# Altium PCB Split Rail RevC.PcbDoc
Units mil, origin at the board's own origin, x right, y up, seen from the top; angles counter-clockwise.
Board outline 1500 x 1405 mil, 2 copper layers (Top Layer, Bottom Layer); 41 components, 22 nets, 98 pads, 37 vias.
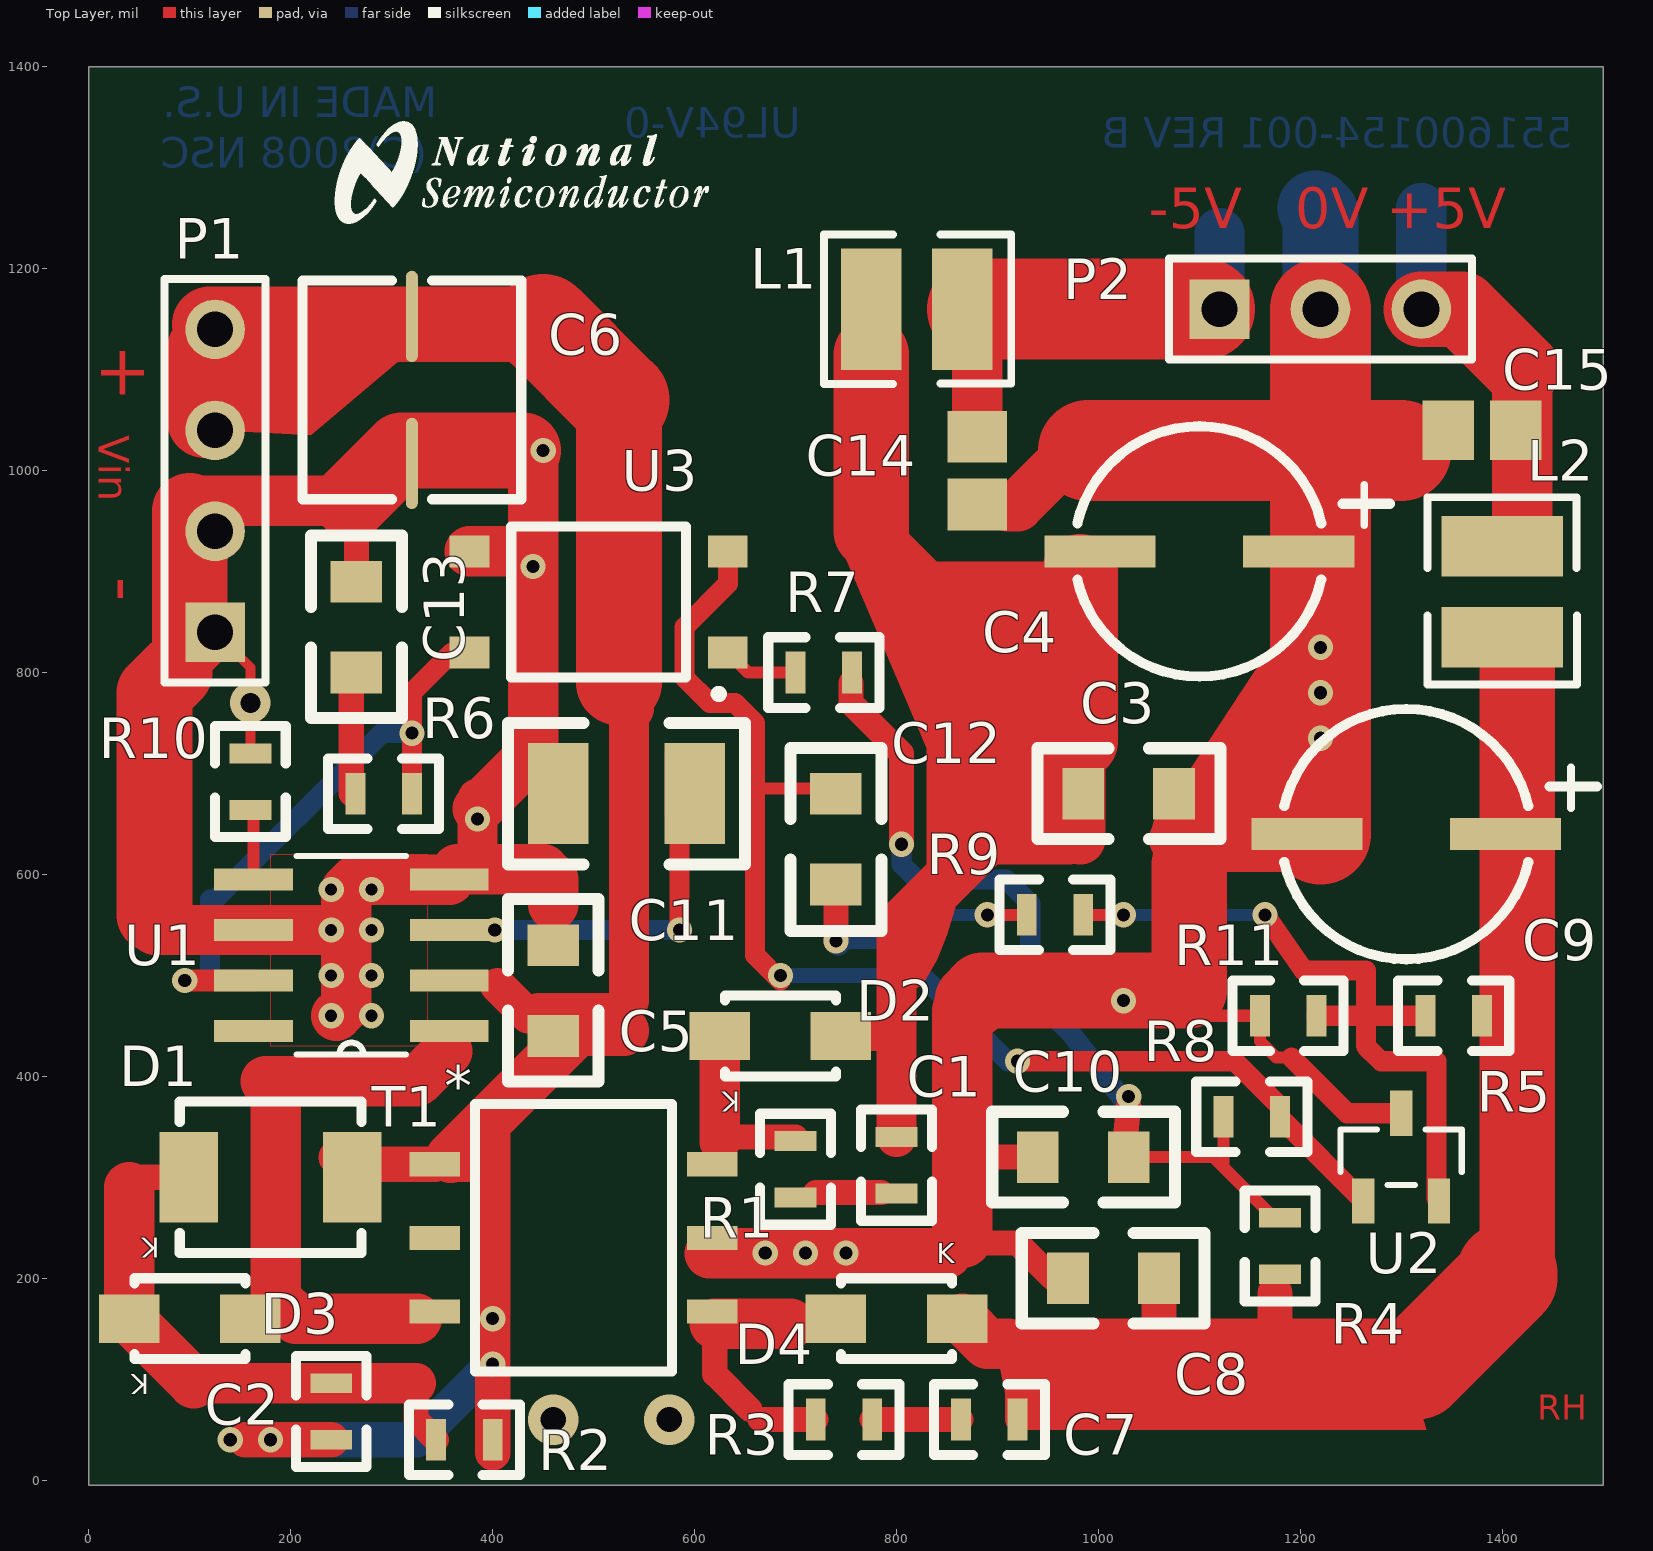
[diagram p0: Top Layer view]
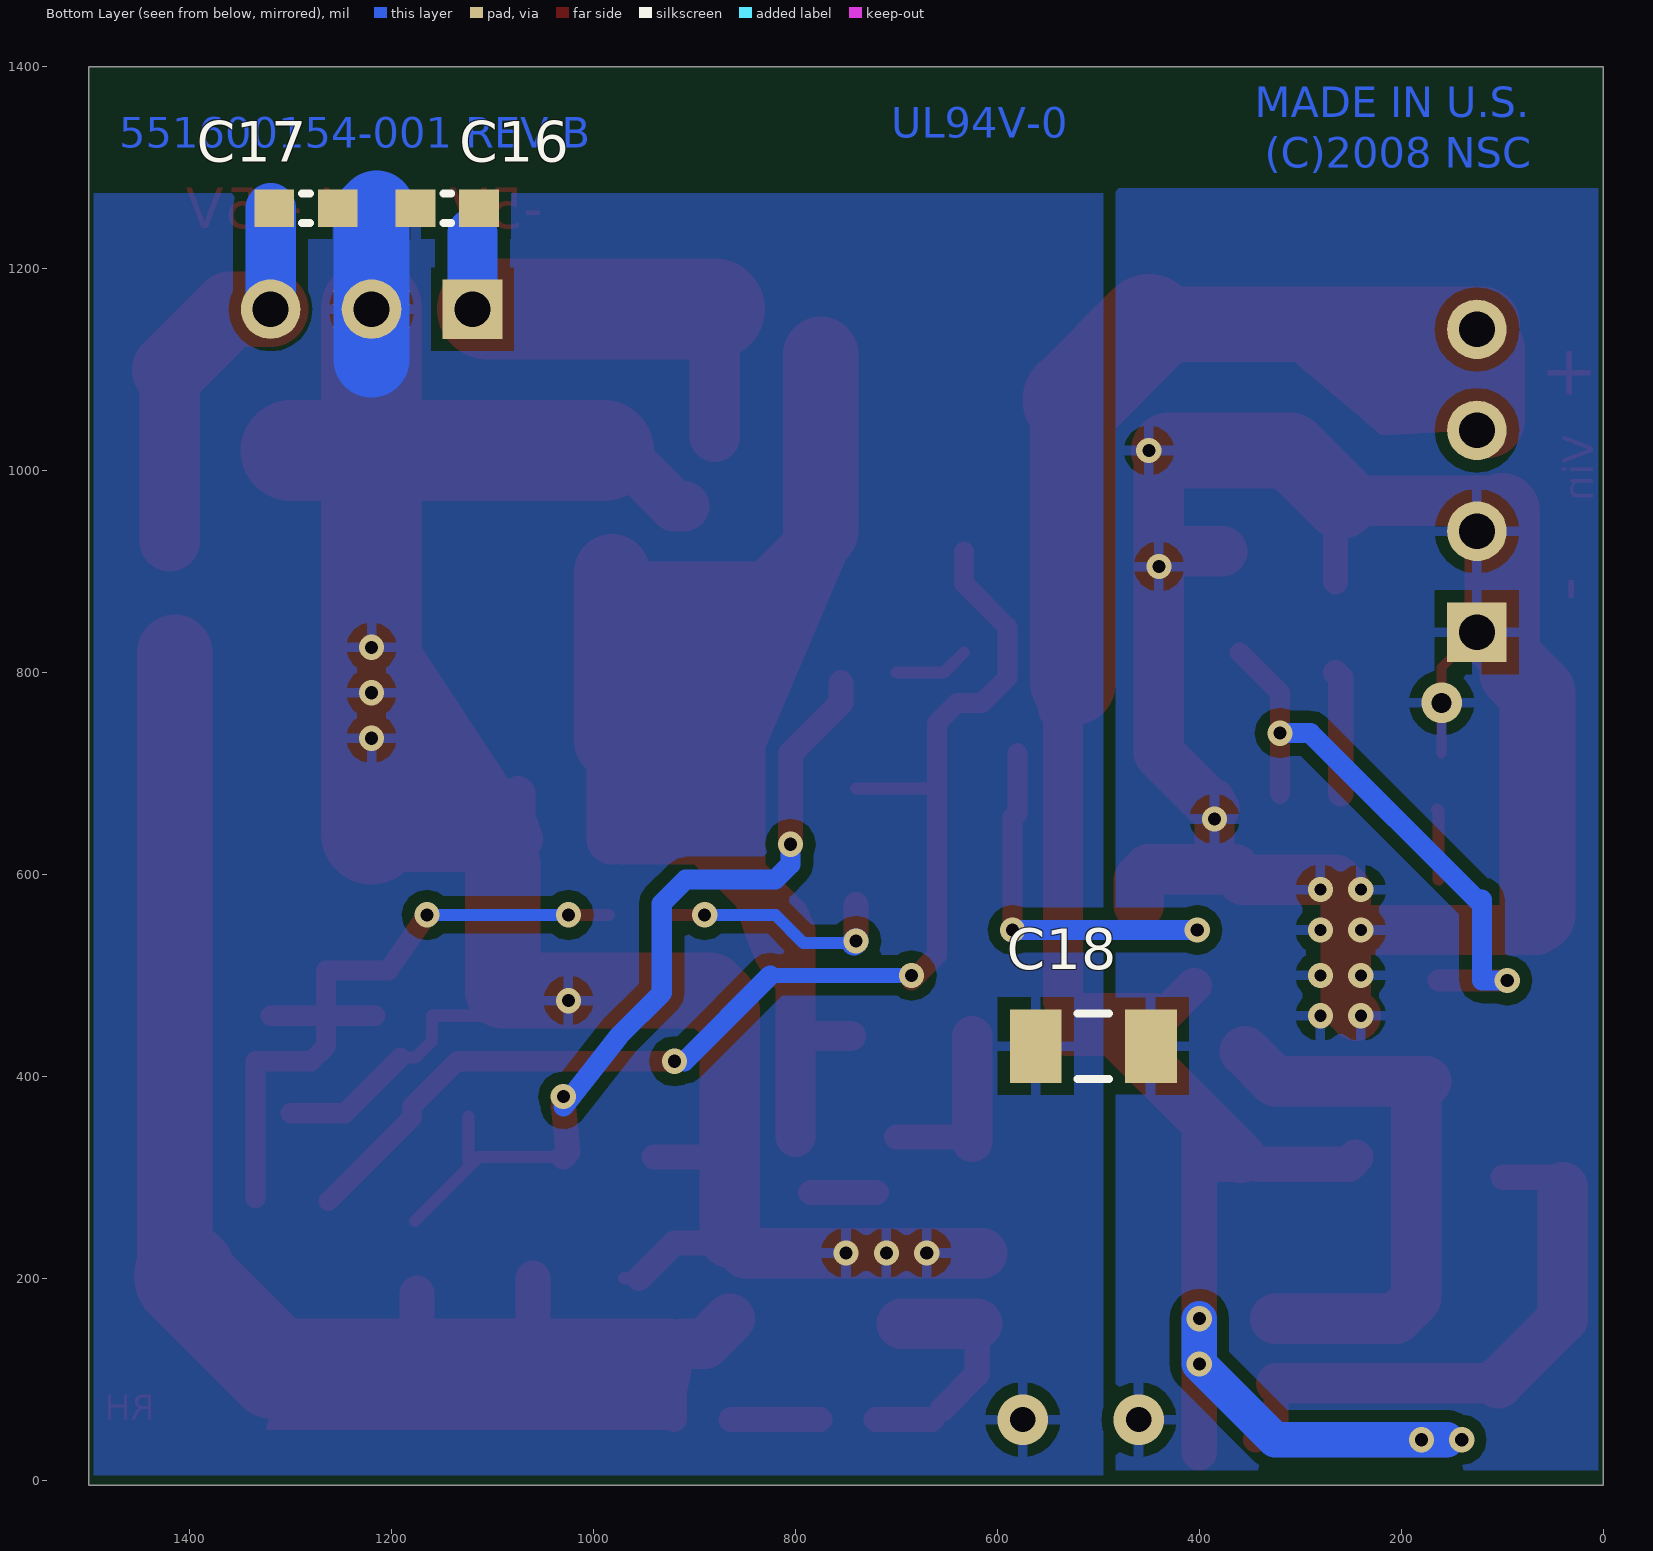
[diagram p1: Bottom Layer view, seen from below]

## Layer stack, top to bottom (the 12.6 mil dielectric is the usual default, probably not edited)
Top Layer: signal copper 1.4
Dielectric: core 12.6, FR-4, Dk 4.8
Bottom Layer: signal copper 1.4

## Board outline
0,-5 0,1400 1500,1400 1500,-5

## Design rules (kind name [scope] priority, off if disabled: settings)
Clearance "DC Power <25W" [All] p1: gap=12
Clearance [All] p2: gap=5
ComponentClearance [All] p1: gap=10 collisioncheckmode=0 verticalgap=10
PolygonConnect [All] p1: connectstyle=Relief reliefconductorwidth=10 reliefentries=4 polygonreliefangle="90 Angle"
RoutingVias [All] p1: holewidth=13 width=25 viastyle="Through Hole" minholewidth=12 minwidth=25 maxholewidth=28 maxwidth=50
SMDNeckDown [All] p1: percent=750.000
SolderMaskExpansion [All] p1: expansion=4
TestPointUsage [All] p1: valid=0 allowmultiple=FALSE
Testpoint [All] p1: side=15 testpointundercomponent=TRUE minsize=10 maxsize=100 preferedsize=60 minholesize=0 maxholesize=40 preferedholesize=32 testpointgrid=1 style=1023 order=0-112345678
Width "Schematic Width Constraint" [InNet('NetC2_1')] p1: maxlimit=100 minlimit=10 preferedwidth=40
Width Ground_Out [InNet('NetC3_2')] p2: maxlimit=100 minlimit=10 preferedwidth=50
Width Ground_In [InNet('GND')] p3: maxlimit=100 minlimit=10 preferedwidth=35
Width [All] p4: maxlimit=200 minlimit=10 preferedwidth=20
18 further rules are at their usual default settings.

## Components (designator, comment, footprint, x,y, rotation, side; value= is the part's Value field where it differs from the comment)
C1 "WB_CAPACITOR" 0603#1 800,340 r270 top
C2 "WB_CAPACITOR" 0603#1 240,40 r90 top
C3 "WB_CAPACITOR" 0805#1 985,680 r0 top
C4 "WB_CAP_POLARIZED" SM_RADIAL_D 1100,920 r90 top
C5 "WB_CAPACITOR" 0805#1 460,440 r90 top
C6 "WB_CAP_POLARIZED" MZA 320,1080 r180 top
C7 "WB_CAPACITOR" 0603#1 920,60 r180 top
C8 "WB_CAPACITOR" 0805#1 1060,200 r180 top
C9 "WB_CAP_POLARIZED" SM_RADIAL_D 1305,640 r90 top
C10 "WB_CAPACITOR" 0805#1 940,320 r0 top
C11 "WB_CAPACITOR" 1210 600,680 r180 top
C12 "WB_CAPACITOR" 0805#1 740,680 r270 top
C13 "WB_CAPACITOR" 0805#1 265,800 r90 top
C14 "WB_CAPACITOR" 0805#2 880,1000 r270 top
C15 "WB_CAPACITOR" 0805#2 1380,1040 r0 top
C16 "WB_CAPACITOR" 0603#2 1145,1260 r0 bottom
C17 "WB_CAPACITOR" 0603#2 1285,1260 r0 bottom
C18 "WB_CAPACITOR" 1206 505,430 r180 bottom
D1 "33V Zener, SMB, 1Wmin" SMB 180,300 r180 top
D2 "WB_DIODE_SCHOTTKY" SOD-123 685,440 r180 top
D3 "BAT41ZFILM" SOD-123 100,160 r180 top
D4 "WB_DIODE_SCHOTTKY" SOD-123 800,160 r0 top
L1 "WB_INDUCTOR" ME3220 820,1160 r180 top
L2 "WB_INDUCTOR" ME3220 1400,880 r270 top
P1 "Header 4" HDR1X4 125,840 r90 top
P2 "Header 3" HDR1X3 1120,1160 r0 top
R1 "WB_Resistor" 0603#1 700,280 r90 top
R2 "WB_Resistor" 0603#1 400,40 r180 top
R3 "WB_Resistor" 0603#1 775.98,60 r180 top
R4 "WB_Resistor" 0603#1 1180,260 r270 top
R5 "WB_Resistor" 0603#1 1380,460 r180 top
R6 "WB_Resistor" 0603#1 320,680 r180 top
R7 "WB_Resistor" 0603#1 700,800 r0 top
R8 "WB_Resistor" 0603#1 1180,360 r180 top
R9 "WB_Resistor" 0603#1 985,560 r180 top
R10 "WB_Resistor" 0603#1 160,720 r270 top
R11 "WB_Resistor" 0603#1 1160,460 r0 top
T1 "RENCO_EP5" S32890 480,240 r0 top
U1 "LM5001MA" M08A 260,520 r180 top
U2 "LM431Z" MF03A 1300,320 r0 top
U3 "FODM121" FOD121 505,870 r180 top

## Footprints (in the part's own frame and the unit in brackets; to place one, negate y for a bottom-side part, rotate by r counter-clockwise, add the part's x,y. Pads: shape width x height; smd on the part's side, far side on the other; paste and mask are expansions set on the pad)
0603#1 [mm]
  rect 0.5x1.05 smd: 1(0,0) 2(1.422,0)
  silkscreen extent -0.69,-0.89 2.11,0.89
0603#2 [mm] "0603 from SM-752 data"
  rect 1x0.95 smd: 1(-0.8,0) 2(0.8,0)
  silkscreen extent -0.1,-0.38 0.1,0.38, body extent -0.88,-0.48 0.87,0.48, height 0.85
0805#1 [mm]
  rect 1.05x1.3 smd: 1(0,0) 2(2.286,0)
  silkscreen extent -1.15,-1.14 3.45,1.14
0805#2 [mm] "0805 from SM-752 data"
  rect 1.3x1.5 smd: 1(-0.85,0) 2(0.85,0)
  body extent -1.1,-0.72 1.1,0.72, height 1.1
1206 [mm] "1206 from SM-752 data"
  rect 1.3x1.85 smd: 1(-1.45,0) 2(1.45,0)
  silkscreen extent -0.4,-0.82 0.4,0.82, body extent -1.7,-0.9 1.7,0.9, height 1.35
1210 [mil]
  rect 60x100 smd: 1(0,0) 2(135,0)
  silkscreen extent -50,-70 185,70
FOD121 [mm] "Fairchild OptoCoupler"
  rect 1x0.8 smd: 1(-3.25,1.27) 2(-3.25,-1.27) 3(3.25,-1.27) 4(3.25,1.27)
  silkscreen extent -3.1,-1.9 2.2,2.39, body extent -3.85,-2.03 3.85,2.03, height 2.3
HDR1X3 [mm] "Connector; Header; 3 Position"
  rect 1.5x1.5 hole 0.9: 1(0,0)
  round 1.5 hole 0.9: 2(2.54,0) 3(5.08,0)
  silkscreen extent -1.27,-1.27 6.35,1.27
HDR1X4 [mm] "Connector; Header; 4 Position"
  rect 1.5x1.5 hole 0.9: 1(0,0)
  round 1.5 hole 0.9: 2(2.54,0) 3(5.08,0) 4(7.62,0)
  silkscreen extent -1.27,-1.27 8.89,1.27
M08A [mil]
  rect 78x22 smd: 1(-97,75) 2(-97,25) 3(-97,-25) 4(-97,-75) 5(97,-75) 6(97,-25) 7(97,25) 8(97,75)
  silkscreen extent -54,-98 54,98
ME3220 [mm] "Coilcraft SMT Power Inductor ME3220 inductors"
  rect 1.52x3.05 smd: 1(-1.145,0) 2(1.145,0)
  silkscreen extent -2.38,-1.88 2.34,1.88, body extent -1.75,-1.41 1.75,1.4
MF03A [mil]
  rect 22x45 smd: 1(-37.5,-43.5) 2(37.5,-43.5) 3(0,43.5)
  silkscreen extent -60,-28 60,28
MZA [mm]
  oval 0.3x2.3 smd: 1(0,-1.85) 2(0,1.85)
  silkscreen extent -2.75,-2.75 2.75,2.75
S32890 [mm]
  rect 1.27x0.61 smd: 1(-3.493,1.854) 2(-3.493,0) 3(-3.493,-1.854) 4(3.493,-1.854) 5(3.493,0) 6(3.493,1.854)
  silkscreen extent -2.47,-3.36 2.47,3.36
SM_RADIAL_D [mm] "SM_RADIAL_D"
  rect 0.8x2.8 smd: 1(0,-2.5) 2(0,2.5)
  silkscreen extent -3.15,-4.8 3.15,3.07
SMB [mil]
  rect 58x90 smd: 1(-81,0) 2(81,0)
  silkscreen extent -90,-75 90,75
SOD-123 [mil]
  rect 60x48 smd: 1(-60,0) 2(60,0)
  silkscreen extent -55,-40 55,40

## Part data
C1 C7: library part 06035A221JAT2A, "Capacitor"
C2: library part GRM188R71H103KA01D, "Capacitor"
C3 C5 C8 C12 C13: library part C0805C104J5RACTU, "Capacitor"
C4 C9: library part EEV-FK1C470P, "Polarized Capacitor"
C6: library part EMZA500ADA100ME61G, "Polarized Capacitor"
C10: library part TMK212BJ105KG-T, "Capacitor"
C11: library part GRM32RR71H105K, "Capacitor"
C14 C15: library part EMK212BJ106KG-T, "Capacitor"
C16 C17: library part C1608X7R1H103K, "Capacitor"
C18: library part C3216C0G2J332J, "Capacitor"
D1: library part 10BQ100TRPBF, "Schottky Diode"
D2 D3 D4: library part 1N5819HW-7, "Schottky Diode"
L1 L2: library part ME3220-102MLB, "Inductor"
P1: "Header, 4-Pin"
P2: "Header, 3-Pin"
R1 R3: library part CRCW0603120RJNEA, "Resistor"
R2 R8: library part CRCW060310k0JNEA, "Resistor"
R4: library part CRCW060347R0JNEA, "Resistor"
R5 R11: library part CRCW06032k20JNEA, "Resistor"
R6: library part CRCW0603249RFKEA, "Resistor"
R7: library part CRCW0603560RJNEA, "Resistor"
R9: library part CRCW06034k99FKEA, "Resistor"
R10: library part CRCW060320k5FKEA, "Resistor"
T1: "Transformer"
U1: "High Voltage Switch Mode Regulator"
U2: library part LM431CCM3, "Adjustable Precision Zener Shunt Regulator"
U3: "Full Pitch Mini-Flat Package Transistor Output  Optocoupler"

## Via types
v1: diameter 25, hole 13, Top Layer to Bottom Layer, 26 vias
v2: diameter 25, hole 12, Top Layer to Bottom Layer, 8 vias
v3: diameter 50, hole 25, Top Layer to Bottom Layer, 2 vias
v4: diameter 40, hole 20, Top Layer to Bottom Layer, 1 vias

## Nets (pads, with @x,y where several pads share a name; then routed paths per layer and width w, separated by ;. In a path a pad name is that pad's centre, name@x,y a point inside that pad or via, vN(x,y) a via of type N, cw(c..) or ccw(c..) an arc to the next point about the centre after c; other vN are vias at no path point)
GND: C5.2 C6.2 C11.2 C13.2 C18.2 P1.1 P1.2 R10.1 U1.4 U1.6 U3.3 | length 2006.5
  Top Layer w10: P1.1 160,805 R10.1
  Top Layer w25: C13.2 265,975
  Top Layer w40: 385,615 385,675
  Top Layer w50: 65,545 v2(240,545) ; 85,800 P1.1 ; 105,970 260,970 ; v2@245,460 255,470 255,585 265,595 U1.4 ; U1.4@365,605 450,605 460,595 460,570 ; U3.3 425,920 ; v1@385,665 440,720 440,1010
  Top Layer w75: 65,560 65,780 85,800 ; P1.1@100,833.75 100,960 ; 260,970 310,1020 430,1020
  other v1: 385,655 440,905 450,1020
  other v2: 240,460 280,460 240,500 280,500 280,545 240,585 280,585
  other v3: 460,60
  other v4: 160,770
NetC1_1: C1.1 C3.1 C4.2 D2.1 L1.2 | length 1083
  Top Layer w30: D2.1 790,440
  Top Layer w40: C1.1 800,545
  Top Layer w50: 775,940 830,885 950,885 ; 810,555 895,640 ; 981.85,635 981.85,731.85
  Top Layer w60: 895,640 970,640
  Top Layer w75: 775,940 L1.2@775,1115 ; 981.85,731.85 981.85,900
NetC1_2: C1.2 R1.1 | length 65
  Top Layer w25: R1.1@720,285 C1.2@785,285
NetC2_1: C2.1 C5.1 C6.1 D1.1 P1.3 P1.4 R2.1 T1.1 U1.2 | length 2315.7
  Top Layer w35: P1.3@115,1050 P1.3 ; 155,40 C2.1 ; D1.1@245,320 252,313 T1.1 ; T1.1@358.44,319.61 361.18,313 400,313 ; R2.1@400,27 400,340 ; 405,490 C5.1@435,460 ; 445,465 525,465
  Top Layer w40: 535,475 535,765
  Top Layer w50: T1.1@358.44,319.61 483.83,445 530,445 ; 525,775 535,765
  Top Layer w75: P1.3@115,1050 P1.4@115,1120 ; P1.4@120,1145 450,1145
  Top Layer w85: 525,790 525,1070
  Top Layer w100: 450,1145 525,1070
  Bottom Layer w35: 155,40 325,40 v1(400,115) v1(400,160)
  other v1: 140,40 180,40
NetC2_2: C2.2 D1.2 D3.2 R2.2 | length 567.9
  Top Layer w25: 40,290 50,300 D1.2 ; 324.02,95.98 324.02,60 R2.2
  Top Layer w40: 104.02,95.98 324.02,95.98
  Top Layer w50: 40,290 D3.2 104.02,95.98
NetC3_2: C3.2 C4.1 C8.2 C9.2 C10.1 C14.2 C15.1 C16.2 C17.1 C18.1 P2.2 R11.1 T1.5 U2.3 | length 2650.5
  Top Layer w12: C8.2@955,200 C8.2 ; 1067.5,490 1097.5,460 ; 1090,485 1100,500 ; 1092.5,460 R11.1 1160,435 1176.25,418.75 1191.25,418.75
  Top Layer w20: 1191.25,418.75 1246.5,363.5 U2.3
  Top Layer w25: 830,235 920,235 C8.2@955,200 ; 865,320 C10.1
  Top Layer w35: 1075,635 C3.2
  Top Layer w50: 615,225 850,225 ; 865,465 875,475 ; 910,965 920,965 995,1040 ; 1075,635 1080,640
  Top Layer w60: 865,240 865,465
  Top Layer w75: 875,475 885,485 1090,485 1090,610 ; 1090,640 C9.2@1220,640
  Top Layer w100: 990,1020 1300,1020 ; C9.2@1220,640 P2.2
  Bottom Layer w75: 1215,1260 1220,1255 1220,1110.07
  other v1: 670,225 710,225 750,225 1025,475 1220,735 1220,780 1220,825
  other v3: 575,60
NetC7_1: C7.1 C8.1 C9.1 D4.2 L2.2 R4.2 R5.1 | length 1370.8
  Top Layer w25: 910,135 925,135 ; C7.1 920,135
  Top Layer w35: 1060,145 C8.1 ; 1175,150.98 1175,185
  Top Layer w50: D4.2@865,160 890,135 910,135 ; 925,135 1310,135
  Top Layer w75: 1405,205 1415,215 L2.2@1415,820
  Top Layer w100: 1315,110 1405,200 1405,205
NetC7_2: C7.2 R3.1 | length 88
  Top Layer w25: R3.1 C7.2
NetC10_2: C10.2 R4.1 R7.2 R8.2 | length 856.2
  Top Layer w12: C10.2 1114.02,320 R4.1@1177.01,257.01 ; 1124.02,310.98 R8.2
  Top Layer w25: R7.2@755,790 755,770 805,720 v1(805,630) ; C10.2 1025.5,324.98 v1@1030,370
  Bottom Layer w20: v1(805,630) 805,610 820,595 908.75,595 932.5,571.25 932.5,482.5 975,440 v1@1030,370
  other v1: 1030,380
NetC11_1: C11.1 U1.3 | length 355
  Top Layer w20: C11.1@580,660 C11.1@580,720 ; v1(585,545) C11.1@585,657
  Bottom Layer w20: v1(402,545) v1(585,545)
NetC12_1: C12.1 R8.1 U2.1 U3.2 | length 1248.3
  Top Layer w12: 660,685 C12.1@740,685 ; v1@685,495 v1(685,500) ; R8.1@1180,359 R8.1
  Top Layer w20: U3.2 632.95,887.95 590,845 590,795 615,770 640,770 660,750 660,520 v1@685,495 ; v1(920,415) 1135,415 1180,370 R8.1 ; R8.1@1180,359 U2.1
  Bottom Layer w15: v1(685,500) 825,500
  Bottom Layer w20: 825,500 v1@910,415
NetC12_2: C12.2 R9.2 | length 237.4
  Top Layer w12: v1(890,560) R9.2
  Top Layer w25: v1(740,534) C12.2@740,570
  Bottom Layer w12: v1@742,532 792,532 820,560 v1(890,560)
  Bottom Layer w25: v1(740,534) v1@742,532
NetC13_1: C13.1 R6.2 | length 122.1
  Top Layer w25: R6.2@260,680 260,795 C13.1
NetC14_1: C14.1 C16.1 L1.1 P2.1 | length 447.6
  Top Layer w12: L1.1@880,1145.08 L1.1@894.92,1160
  Top Layer w50: C14.1 L1.1@880,1160
  Top Layer w100: L1.1@880,1160 P2.1@1105,1160
  Bottom Layer w50: P2.1 1120,1235
NetC15_2: C15.2 C17.2 L2.1 P2.3 | length 394.8
  Top Layer w60: L2.1@1420,930.08 1420,1100
  Top Layer w75: P2.3 1360,1160 1420,1100
  Bottom Layer w50: P2.3 C17.2@1320,1260
NetD2_2: D2.2 R1.2 T1.6 | length 160
  Top Layer w25: 645,340 R1.2@700,340
  Top Layer w40: 625,335 D2.2
NetD3_1: D3.1 T1.3 U1.1 | length 555.7
  Top Layer w50: 175,395 325,395 355,425 ; 185,395 185,180 205,160 T1.3@325,160
NetD4_1: D4.1 R3.2 T1.4 | length 241.5
  Top Layer w25: T1.4@620,167 620,105 655,70 ; 665,60 R3.2
  Top Layer w50: T1.4@620,155 695,155
NetR5_2: R5.2 R9.1 R11.2 U2.2 | length 704.9
  Top Layer w12: R9.1 v1(1025,560)
  Top Layer w20: v1(1165,560) 1203.33,505 1265,505 1265,430 1280,415 1335,415 U2.2@1335,279 ; R11.2 R5.2@1320,460
  Bottom Layer w12: v1@1020,560 v1(1165,560)
NetR6_1: R6.1 U1.7 U3.4 | length 600
  Top Layer w20: R6.1 320,780 U3.4@360,820
  Top Layer w22: v1(95,495) U1.7
  Bottom Layer w20: v1(95,495) 120,495 120,575 ; 120,570 290,740 v1(320,740)
NetR7_1: R7.1 U3.1 | length 75.3
  Top Layer w12: U3.1 652.95,800 R7.1
NetR10_2: R10.2 U1.5 | length 70.1
  Top Layer w12: U1.5 163,663 R10.2@164.51,664.51
pads on no net: T1.2 U1.8

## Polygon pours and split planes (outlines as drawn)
GND on Top Layer "GND" (solid, remove dead copper, pour order 1001): 180,620 335,620 335,430 180,430
NetC3_2 on Bottom Layer "Bottom Layer-NetC3_2" (solid, pour order 1000): 495,1275 1495,1275 1495,5 495,5
GND on Bottom Layer "GND_Out" (solid, remove dead copper, pour order 1002): 5,1280 5,10 485,10 485,1280

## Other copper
Top Layer:
  region net NetC2_1: 125,1140 125,1040 220,1035 350,1145
  region net NetC3_2: 1210,885 1075,680 1205,640
  region net NetC1_1: 745,925 830,725 830,590 989.35,677.5 997.5,862.5
  region net NetC7_1: 1300,135 1325,50 915,50 900,125
  region net NetC1_1: 825,490 840,515 850,540 865,590 800,545 800,505 800,480
  text "-5V" at 1050,1240 h40
  text "0V" at 1195,1240 h40
  text "+5V" at 1285,1240 h40
  text "+" at 5,1075 h50
  text "Vin" at 10,1035 h30 r270
  text "-" at 50,870 h50 r90
  text "RH" at 1435,60 h25
Bottom Layer:
  text "MADE IN U.S." at 345,1350 h30
  text "UL94V-0" at 705,1330 h30
  text "551600154-001 REV B" at 1470,1320 h30
  text "(C)2008 NSC" at 335,1300 h30

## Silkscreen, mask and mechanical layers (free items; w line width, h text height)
Top Overlay:
  drawing of 24 lines, arcs and shapes, not listed
Mechanical 1:
  the board outline again, w10
  text "Vin" at 20,1075 h25 r270
Drill Drawing:
  text ".Legend" at 1760,-60 h40

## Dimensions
0,-5 to 1500,-5 on Mechanical 2
0,-5 to 0,1400 on Mechanical 2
